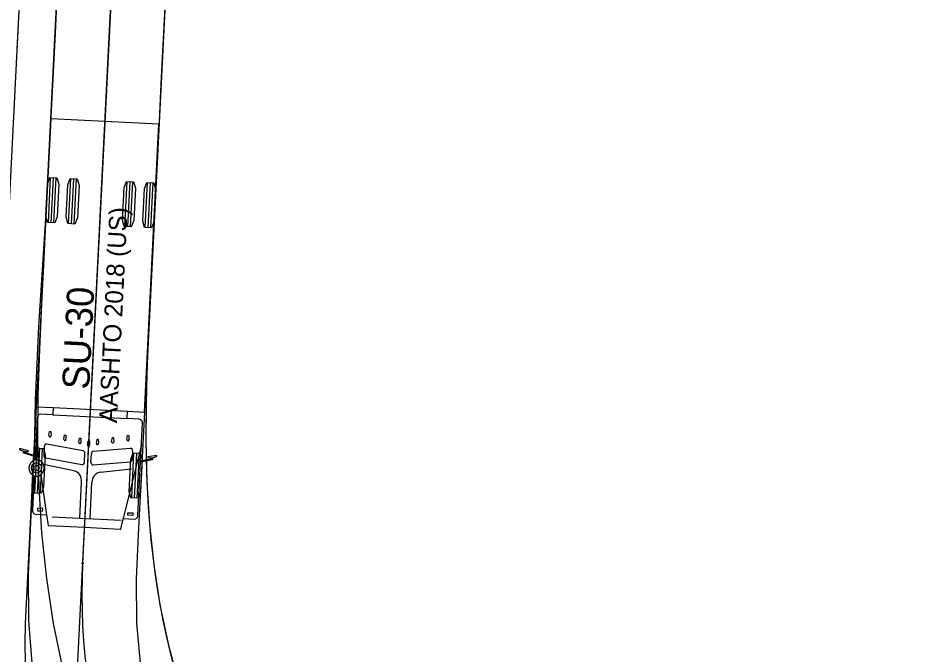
# Model space of a CAD drawing. Extents: x 260275 to 261282, y 610916 to 614143.
# Drawn here: x 261018.9 to 261085.2, y 611654.9 to 611701.9 of the extents above; entities that cross this region are included whole.
import ezdxf

# ---------------------------------------------------------------- set-up
doc = ezdxf.new("R2010")
doc.units = 0
doc.layers.add('GE_X_Alignment', color=7, linetype='Continuous')
doc.layers.add('UT_X_Water_Cells', color=7, linetype='Continuous')

msp = doc.modelspace()

# ---------------------------------------------------------------- linework, layer by layer
at = {"layer": 'GE_X_Alignment'}
msp.add_line((260986.249, 610915.954), (261148.276, 614142.838), dxfattribs=at)
at = {"layer": 'UT_X_Water_Cells'}
for p, q in [((261044.031, 612066.726), (261023.69, 611661.632)), ((261021.157, 611686.79), (261021.324, 611690.119)), ((261021.365, 611686.78), (261021.532, 611690.109)), ((261021.573, 611686.769), (261021.741, 611690.098)), ((261022.655, 611686.715), (261022.822, 611690.044)), ((261022.863, 611686.704), (261023.031, 611690.034)), ((261023.071, 611686.694), (261023.239, 611690.023)), ((261026.817, 611686.506), (261026.984, 611689.835)), ((261027.025, 611686.495), (261027.192, 611689.825)), ((261027.233, 611686.485), (261027.4, 611689.814)), ((261028.315, 611686.431), (261028.482, 611689.76)), ((261028.523, 611686.42), (261028.69, 611689.749)), ((261028.731, 611686.41), (261028.898, 611689.739)), ((261021.519, 611673.135), (261027.004, 611672.859)), ((261021.492, 611672.604), (261026.977, 611672.329)), ((261021.201, 611671.077), (261021.252, 611671.374)), ((261021.252, 611671.374), (261021.334, 611671.37)), ((261021.334, 611671.37), (261021.355, 611671.069)), ((261022.306, 611670.811), (261022.357, 611671.108)), ((261022.357, 611671.108), (261022.44, 611671.104)), ((261022.44, 611671.104), (261022.461, 611670.803)), ((261023.413, 611670.573), (261023.464, 611670.87)), ((261023.464, 611670.87), (261023.546, 611670.866)), ((261023.546, 611670.866), (261023.567, 611670.565)), ((261025.833, 611670.62), (261025.884, 611670.931)), ((261025.884, 611670.931), (261025.966, 611670.927)), ((261025.966, 611670.927), (261025.987, 611670.612)), ((261026.959, 611670.788), (261027.01, 611671.085)), ((261027.01, 611671.085), (261027.092, 611671.081)), ((261027.092, 611671.081), (261027.113, 611670.78)), ((261020.245, 611670.788), (261020.462, 611669.255)), ((261020.853, 611670.238), (261020.822, 611669.622)), ((261023.718, 611669.945), (261021.045, 611670.431)), ((261024.052, 611670.372), (261024.103, 611670.67)), ((261024.103, 611670.67), (261024.185, 611670.665)), ((261024.185, 611670.665), (261024.206, 611670.364)), ((261024.708, 611670.508), (261024.759, 611670.805)), ((261024.759, 611670.805), (261024.841, 611670.801)), ((261024.841, 611670.801), (261024.862, 611670.5)), ((261028.035, 611670.397), (261026.695, 611664.93)), ((261020.154, 611666.815), (261020.321, 611670.144)), ((261020.362, 611666.805), (261020.529, 611670.134)), ((261020.57, 611666.794), (261020.738, 611670.123)), ((261023.828, 611669.119), (261023.859, 611669.735)), ((261024.303, 611669.096), (261024.334, 611669.711)), ((261024.496, 611669.906), (261027.204, 611670.122)), ((261027.312, 611666.456), (261027.479, 611669.785)), ((261027.376, 611669.911), (261027.345, 611669.295)), ((261027.52, 611666.445), (261027.687, 611669.775)), ((261027.728, 611666.435), (261027.895, 611669.764)), ((261023.051, 611668.469), (261020.795, 611668.93)), ((261020.963, 611669.413), (261023.637, 611668.927)), ((261027.183, 611669.101), (261024.475, 611668.885)), ((261025.011, 611668.371), (261027.29, 611668.602)), ((261020.11, 611668.089), (261019.983, 611665.57)), ((261020.613, 611668.18), (261021.031, 611665.214)), ((261023.475, 611664.968), (261023.608, 611667.633)), ((261024.239, 611664.93), (261024.373, 611667.595)), ((261020.366, 611665.704), (261020.356, 611665.51)), ((261020.744, 611665.685), (261020.366, 611665.704)), ((261020.734, 611665.491), (261020.744, 611665.685)), ((261020.356, 611665.51), (261020.734, 611665.491)), ((261021.44, 611665.07), (261026.539, 611664.814)), ((261027.018, 611665.175), (261027.028, 611665.369)), ((261027.396, 611665.156), (261027.018, 611665.175)), ((261027.028, 611665.369), (261027.406, 611665.35)), ((261027.406, 611665.35), (261027.396, 611665.156))]:
    msp.add_line(p, q, dxfattribs=at)
for points in [[(261039.447, 612110.045), (261018.12, 611685.301)], [(261019.48, 611654.314), (261019.448, 611655.737), (261019.467, 611657.158), (261020.156, 611670.999), (261020.22, 611673.715), (261020.321, 611676.422), (261020.463, 611679.115), (261020.965, 611687.133), (261041.34, 612092.893)], [(261049.322, 612092.345), (261028.546, 611678.469), (261028.443, 611675.866), (261028.378, 611673.294), (261028.366, 611670.756), (261028.416, 611668.253), (261028.538, 611665.785), (261028.627, 611664.565), (261028.737, 611663.354), (261028.869, 611662.152), (261029.021, 611660.959), (261029.196, 611659.777), (261029.393, 611658.604), (261029.614, 611657.442), (261029.857, 611656.29), (261030.125, 611655.149), (261030.416, 611654.02)], [(261021.818, 611704.106), (261021.651, 611700.778), (261021.484, 611697.449), (261021.317, 611694.121), (261021.15, 611690.792), (261020.982, 611687.463), (261020.815, 611684.135), (261020.648, 611680.806), (261020.481, 611677.478), (261020.314, 611674.149), (261020.147, 611670.82), (261019.98, 611667.492), (261019.812, 611664.163), (261019.656, 611660.814), (261019.685, 611657.393), (261019.965, 611653.952)], [(261021.818, 611704.11), (261021.651, 611700.781), (261021.484, 611697.452), (261021.317, 611694.124), (261021.15, 611690.795), (261020.983, 611687.466), (261020.815, 611684.138), (261020.648, 611680.807), (261020.495, 611677.447), (261020.391, 611674.063), (261020.366, 611670.667), (261020.448, 611667.271), (261020.656, 611663.885), (261021.01, 611660.517), (261021.521, 611657.179), (261022.202, 611653.88)], [(261029.808, 611703.705), (261029.641, 611700.377), (261029.474, 611697.048), (261029.307, 611693.719), (261029.139, 611690.391), (261028.972, 611687.062), (261028.805, 611683.734), (261028.638, 611680.405), (261028.471, 611677.076), (261028.304, 611673.748), (261028.137, 611670.419), (261027.97, 611667.09), (261027.802, 611663.762), (261027.647, 611660.453), (261027.678, 611657.213), (261027.951, 611654.015)], [(261029.808, 611703.708), (261029.641, 611700.38), (261029.474, 611697.051), (261029.307, 611693.723), (261029.14, 611690.394), (261028.973, 611687.065), (261028.805, 611683.737), (261028.639, 611680.41), (261028.489, 611677.123), (261028.389, 611673.89), (261028.366, 611670.713), (261028.441, 611667.591), (261028.631, 611664.526), (261028.947, 611661.518), (261029.399, 611658.57), (261029.995, 611655.687), (261030.74, 611652.873)], [(261019.006, 611702.93), (261018.838, 611699.601)], [(261027.875, 611672.283), (261026.98, 611672.328), (261026.977, 611672.332), (261027.004, 611672.859), (261027.015, 611672.859), (261028.256, 611672.797), (261029.324, 611694.056), (261025.329, 611694.257), (261021.334, 611694.458), (261020.266, 611673.198), (261021.508, 611673.135), (261021.519, 611673.134), (261021.492, 611672.608), (261021.489, 611672.604), (261020.594, 611672.649)], [(261020.324, 611672.347), (261020.184, 611669.576), (261020.179, 611669.564), (261019.374, 611669.825), (261019.374, 611669.825)], [(261028.806, 611669.351), (261028.806, 611669.351), (261027.979, 611669.173), (261027.975, 611669.185), (261028.114, 611671.956)], [(261019.363, 611669.845), (261019.365, 611669.89), (261019.365, 611669.89), (261019.683, 611669.883), (261019.685, 611669.883), (261019.688, 611669.938), (261019.685, 611669.94), (261019.037, 611670.112), (261019.034, 611670.112), (261019.031, 611670.047), (261019.319, 611669.901), (261019.319, 611669.9), (261019.318, 611669.853)], [(261019.354, 611669.778), (261019.355, 611669.778), (261020.174, 611669.51), (261020.18, 611669.498), (261020.169, 611669.27)], [(261028.865, 611669.374), (261028.868, 611669.421), (261028.868, 611669.421), (261029.169, 611669.538), (261029.173, 611669.603), (261029.17, 611669.603), (261028.508, 611669.497), (261028.505, 611669.496), (261028.502, 611669.44), (261028.504, 611669.44), (261028.821, 611669.415), (261028.821, 611669.415), (261028.818, 611669.371)], [(261027.773, 611665.179), (261027.971, 611669.107), (261027.978, 611669.119), (261028.82, 611669.303), (261028.821, 611669.303)], [(261020.221, 611665.255), (261021.028, 611665.214), (261021.032, 611665.209), (261021.142, 611664.432), (261021.184, 611664.427), (261023.824, 611664.295), (261026.464, 611664.162), (261026.507, 611664.162), (261026.694, 611664.925), (261026.699, 611664.929), (261027.505, 611664.889)]]:
    msp.add_lwpolyline(points, dxfattribs=at)
for points in [[(261021.625, 611686.767), (261021.106, 611686.793), (261020.973, 611687.267), (261021.093, 611689.664), (261021.273, 611690.122), (261021.792, 611690.096), (261021.925, 611689.622), (261021.805, 611687.225)], [(261023.123, 611686.691), (261022.604, 611686.717), (261022.471, 611687.191), (261022.591, 611689.588), (261022.771, 611690.047), (261023.29, 611690.02), (261023.423, 611689.547), (261023.303, 611687.15)], [(261027.284, 611686.482), (261026.765, 611686.508), (261026.632, 611686.982), (261026.752, 611689.379), (261026.932, 611689.838), (261027.452, 611689.812), (261027.585, 611689.338), (261027.464, 611686.941)], [(261028.783, 611686.407), (261028.263, 611686.433), (261028.13, 611686.907), (261028.251, 611689.304), (261028.43, 611689.762), (261028.95, 611689.736), (261029.083, 611689.262), (261028.962, 611686.865)], [(261020.622, 611666.792), (261020.103, 611666.818), (261019.97, 611667.292), (261020.09, 611669.689), (261020.27, 611670.147), (261020.789, 611670.121), (261020.922, 611669.647), (261020.802, 611667.25)], [(261027.78, 611666.432), (261027.26, 611666.458), (261027.127, 611666.932), (261027.248, 611669.329), (261027.427, 611669.788), (261027.947, 611669.761), (261028.08, 611669.288), (261027.96, 611666.891)]]:
    msp.add_lwpolyline(points, close=True, dxfattribs=at)
for centre, radius in [((261020.284, 611668.672), 0.374), ((261020.284, 611668.672), 0.193), ((261023.69, 611661.632), 0.0417), ((261023.69, 611661.632), 0.0417)]:
    msp.add_circle(centre, radius, dxfattribs=at)
for centre, radius, start, end in [((261020.646, 611672.331), 0.323, 99.2771, 177.1255), ((261027.791, 611671.972), 0.323, 357.1255, 74.97391), ((261021.289, 611671.054), 0.091, 165.44206, 259.60593), ((261021.265, 611671.055), 0.0909, 274.60942, 8.84462), ((261021.037, 611670.247), 0.184, 87.71808, 182.58934), ((261022.394, 611670.788), 0.091, 165.44206, 259.60593), ((261022.371, 611670.789), 0.0909, 274.60942, 8.84462), ((261023.501, 611670.55), 0.091, 165.44206, 259.60593), ((261023.477, 611670.551), 0.0909, 274.60942, 8.84462), ((261024.14, 611670.349), 0.091, 165.44206, 259.60593), ((261024.116, 611670.35), 0.091, 274.64508, 8.80895), ((261024.796, 611670.485), 0.0909, 165.40639, 259.64159), ((261024.772, 611670.486), 0.091, 274.64508, 8.80895), ((261025.921, 611670.611), 0.0909, 165.40639, 259.64159), ((261025.897, 611670.612), 0.091, 274.64508, 8.80895), ((261027.047, 611670.765), 0.0909, 165.40639, 259.64159), ((261027.023, 611670.766), 0.091, 274.64508, 8.80895), ((261019.337, 611669.816), 0.0418, 117.61865, 294.63358), ((261019.331, 611669.817), 0.0434, 11.03902, 41.7118), ((261021.013, 611669.599), 0.193, 173.06859, 254.98308), ((261023.668, 611669.759), 0.193, 353.06366, 74.98801), ((261024.527, 611669.715), 0.193, 99.26299, 181.18734), ((261027.193, 611669.938), 0.184, 351.66167, 86.53293), ((261020.351, 611668.669), 0.628, 106.8788, 247.3705), ((261020.289, 611668.759), 0.524, 49.38452, 103.18459), ((261020.216, 611668.683), 0.63, 356.4803, 48.88311), ((261023.644, 611669.111), 0.184, 267.72364, 2.58377), ((261024.486, 611669.069), 0.184, 171.66723, 266.52737), ((261027.152, 611669.291), 0.193, 279.26792, 1.18241), ((261028.848, 611669.339), 0.0434, 132.53921, 163.21198), ((261028.842, 611669.339), 0.0418, 239.61742, 56.63235), ((261020.216, 611668.668), 0.629, 309.17109, 357.86038), ((261022.841, 611667.725), 0.773, 353.15088, 74.23504), ((261025.146, 611667.61), 0.773, 100.01597, 181.10013), ((261020.28, 611668.586), 0.526, 251.07067, 309.31667), ((261020.262, 611665.533), 0.282, 172.49767, 261.5771), ((261027.492, 611665.17), 0.282, 272.67391, 1.75333), ((261068.634, 611659.376), 45, 177.1255, 267.08254)]:
    msp.add_arc(centre, radius, start, end, dxfattribs=at)

# ---------------------------------------------------------------- texts
for s, height, p in [('AASHTO 2018 (US)', 1.33333, (261026.219, 611671.97)), ('SU-30', 2, (261024.173, 611674.433))]:
    msp.add_text(s, height=height, rotation=87.1255, dxfattribs=at).set_placement(p)

doc.saveas('drawing.dxf')
